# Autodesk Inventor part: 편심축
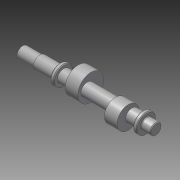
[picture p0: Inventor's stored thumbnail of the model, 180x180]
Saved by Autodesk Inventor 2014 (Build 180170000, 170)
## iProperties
Created: 2021-06
Part Number: 편심축
Material: 강철, 연강
Document SubType Name: Modeling
Designer: mdu-edu
Density: 7.86 g/cm^3
Appearance: 강철
Author: mdu-edu
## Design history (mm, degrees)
sketch "스케치1"
  geometry: L1 (0, 0)-(180, 0); L2 (180, 0)-(180, -7.5); L3 (180, -7.5)-(167, -7.5); L4 (167, -7.5)-(167, -13); L5 (167, -13)-(162, -13); L6 (162, -13)-(162, -8.5); L7 (162, -8.5)-(56, -8.5); L8 (56, -8.5)-(56, -13); L9 (56, -13)-(51, -13); L10 (51, -13)-(51, -8.5); L11 (51, -8.5)-(24, -8.5); L12 (24, -8.5)-(24, -7.5); L13 (24, -7.5)-(0, -7.5); L14 (0, -7.5)-(0, 0)
  constraints: 28 end point, 6 parallel, 3 horizontal, 3 vertical, 1 collinear, 1 perpendicular
  dimensions: "d0" = 15 diameter of L13 L1; "d2" = 26 diameter of L9 L1; "d3" = 26 diameter of L5 L1; "d4" = 15 diameter of L3 L1; "d5" = 17 diameter of L7 L1; "d6" = 17 diameter of L11 L1; "d7" = 24 distance between parallel lines of L12 L14; "d8" = 51 distance between parallel lines of L14 L10; "d10" = 5 distance of L8.end L9.end; "d11" = 5 distance of L4.end L5.end; "d12" = 13 distance between parallel lines of L4 L2; "d13" = 180 distance between parallel lines of L14 L2
revolve "회전1" sketch "스케치1" stored, may be unused: angle "d14" = 90 deg
node "작업 평면1"
sketch "스케치2"
  geometry: C1 r 17.5 at (0, 5); 1 further point
  constraints: 1 centre point, 1 vertical alignment
  dimensions: "d16" = 35 diameter of C1; "d17" = 5 distance of C1.centre point (0, 0)
extrude "돌출1" join sketch "스케치2" distance "d18" = 17; taper "d19" = 0 deg
node "작업 평면2"
sketch "스케치3"
  geometry: C1 r 15 at (0, -5); 1 further point
  constraints: 1 centre point, 1 vertical alignment
  dimensions: "d21" = 30 diameter of C1; "d22" = 5 distance of point (0, 0) C1.centre
extrude "돌출2" join sketch "스케치3" distance "d23" = 17; taper "d24" = 0 deg
chamfer "모따기1" distance "d29" = 1; stored, may be unused: second distance "d30" = 2, angle "d31" = 45 deg
node "작업 평면3"
sketch "스케치4"
  geometry: L1 (-5.5, 2.5)-(12, 2.5); L2 (12, 2.5)-(12, -2.5); L3 (12, -2.5)-(-5.5, -2.5); L4 (12, 6.5)-(12, -6.5) reference; A1 r 2.5 centre (-5.5, 0) between (-5.5, 2.5) and (-5.5, -2.5); 1 further point
  constraints: 6 end point, 2 point on circle, 2 tangent, 1 centre point, 1 collinear, 1 horizontal, 1 horizontal alignment, 1 midpoint, 1 parallel, 1 perpendicular
  dimensions: "d25" = 5 diameter of A1; "d32" = 20 dimension on A1 L4
extrude "돌출3" cut sketch "스케치4" distance "d27" = 3; taper "d28" = 0 deg
fillet "모깎기1" dims "d33" = 0.6
fillet "모깎기2" dims "d34" = 1
node "솔리드1"
other parameters: "d15" = -70.5, "d20" = -32.5
